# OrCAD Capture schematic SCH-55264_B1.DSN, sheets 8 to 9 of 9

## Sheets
8 07 LVDS_CONNECTORS: size C
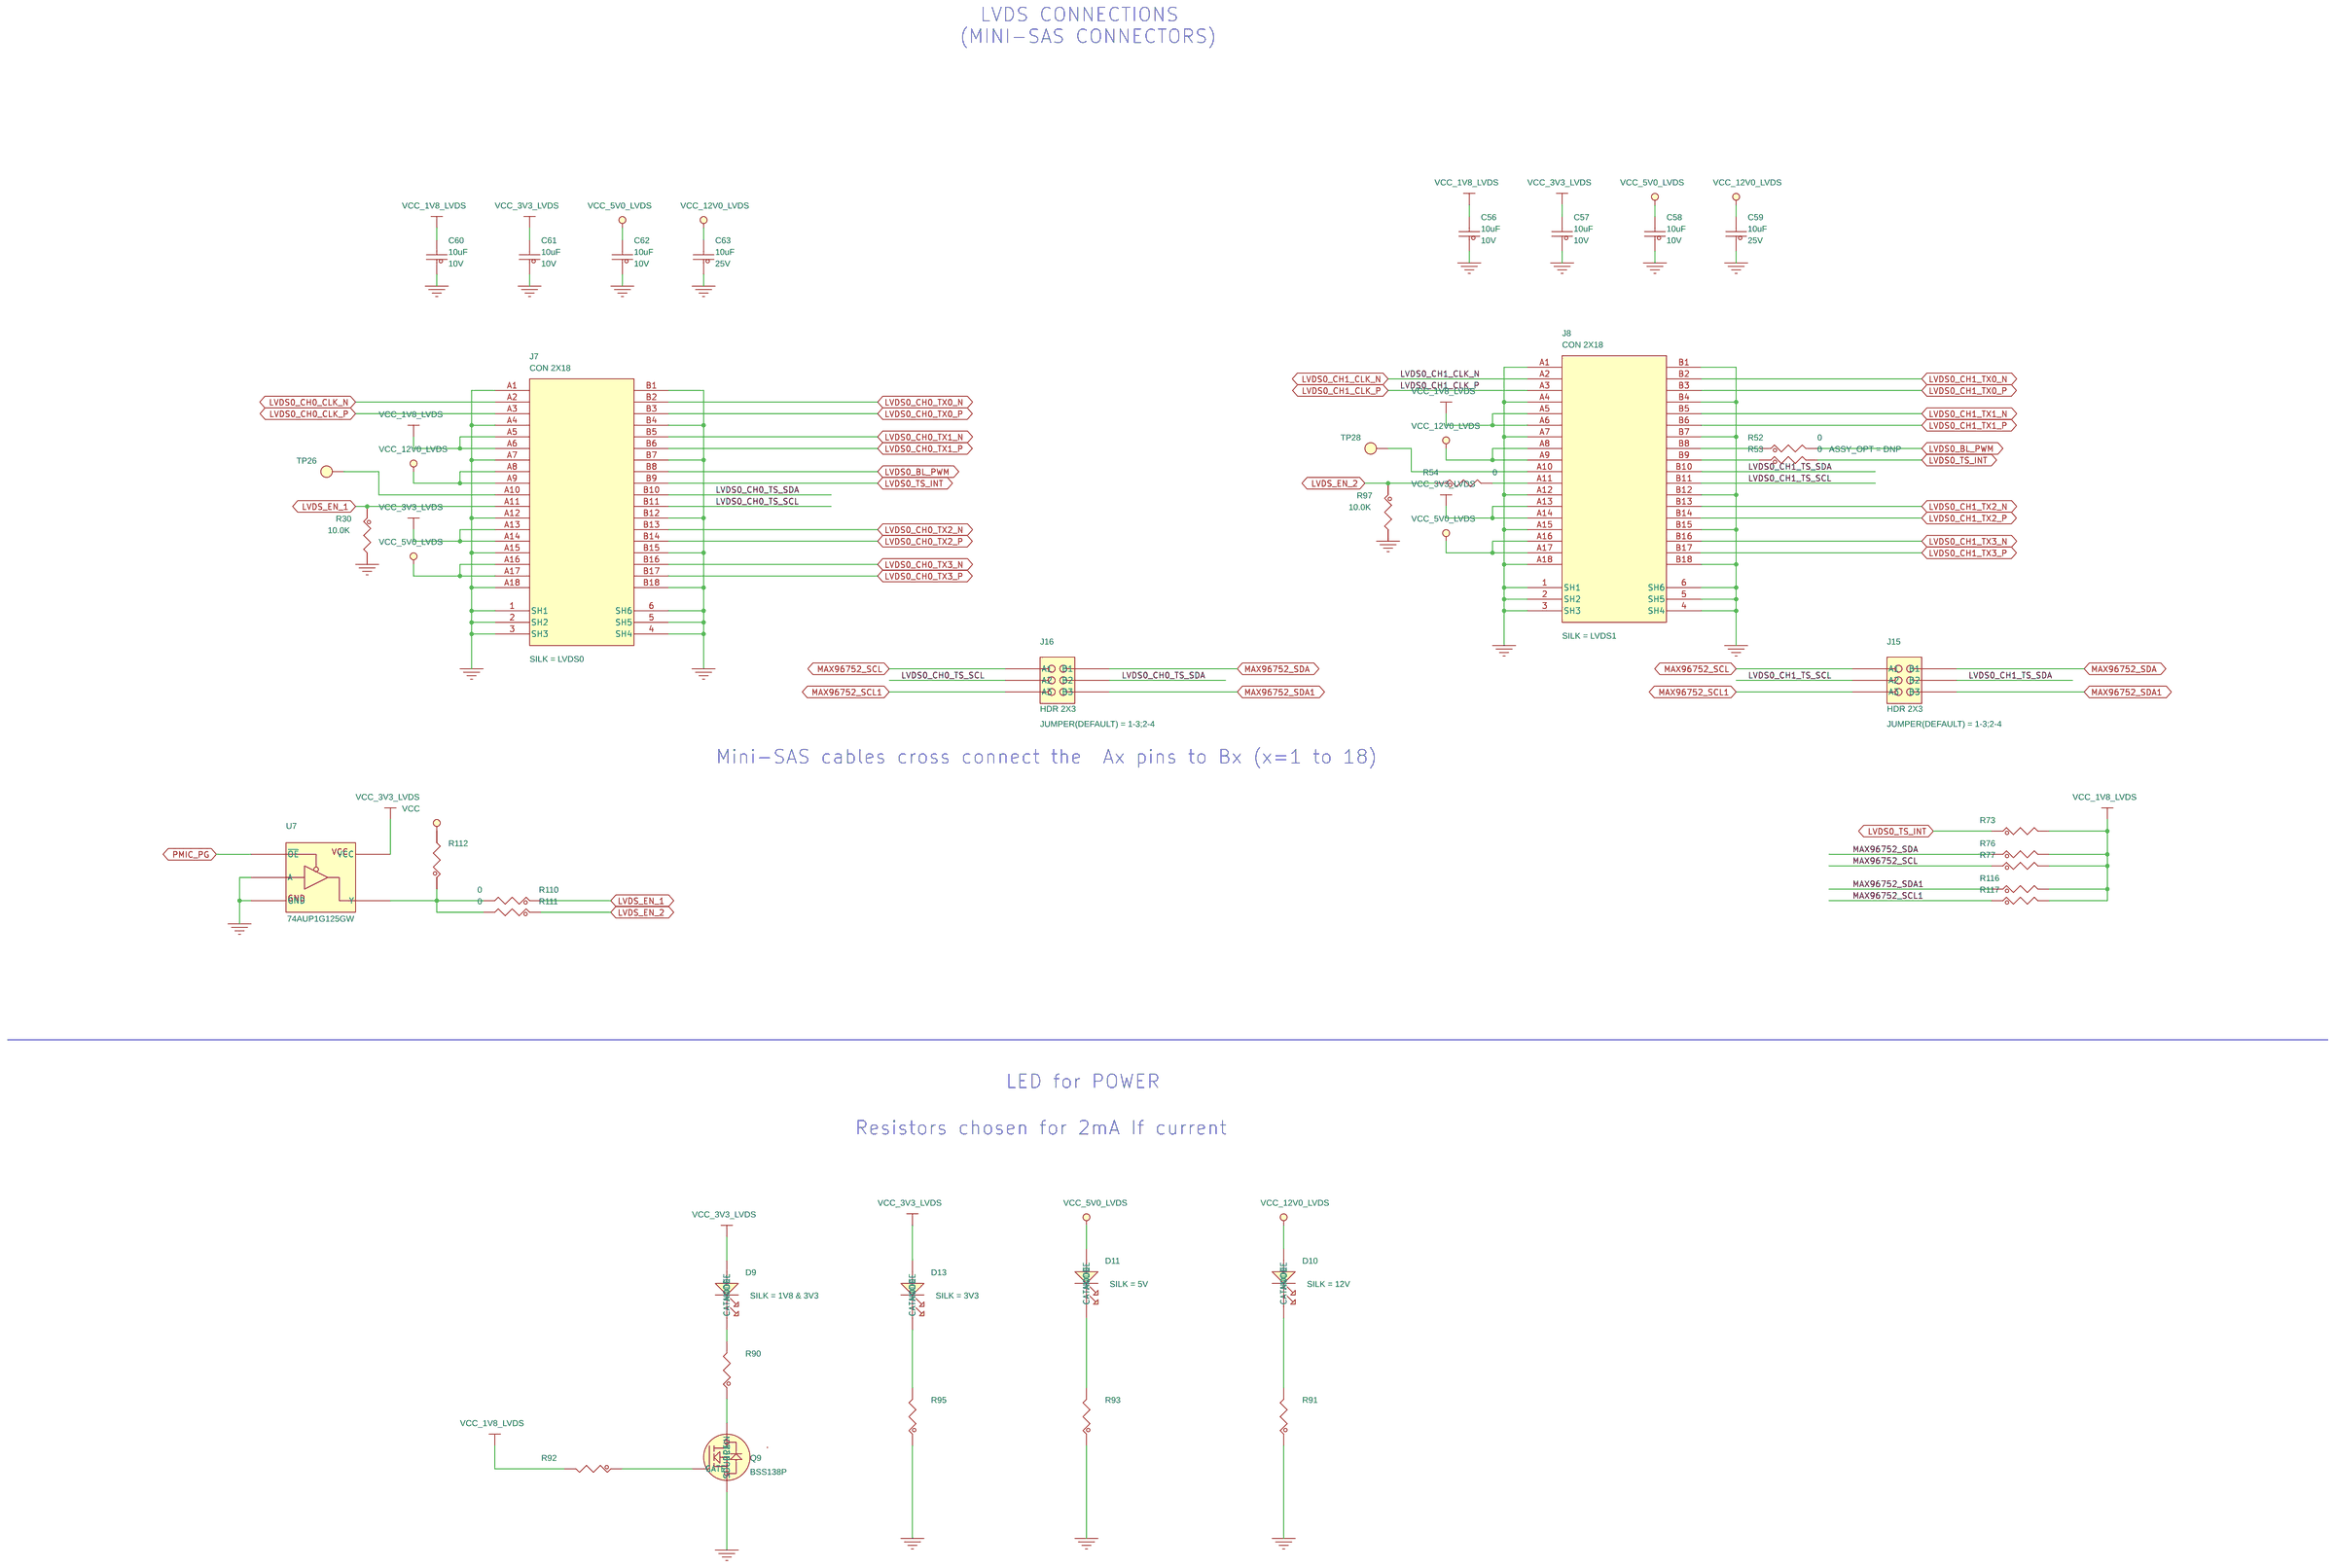
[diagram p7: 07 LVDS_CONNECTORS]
9 08 PMIC_LVDS_SUPPLIES: size C
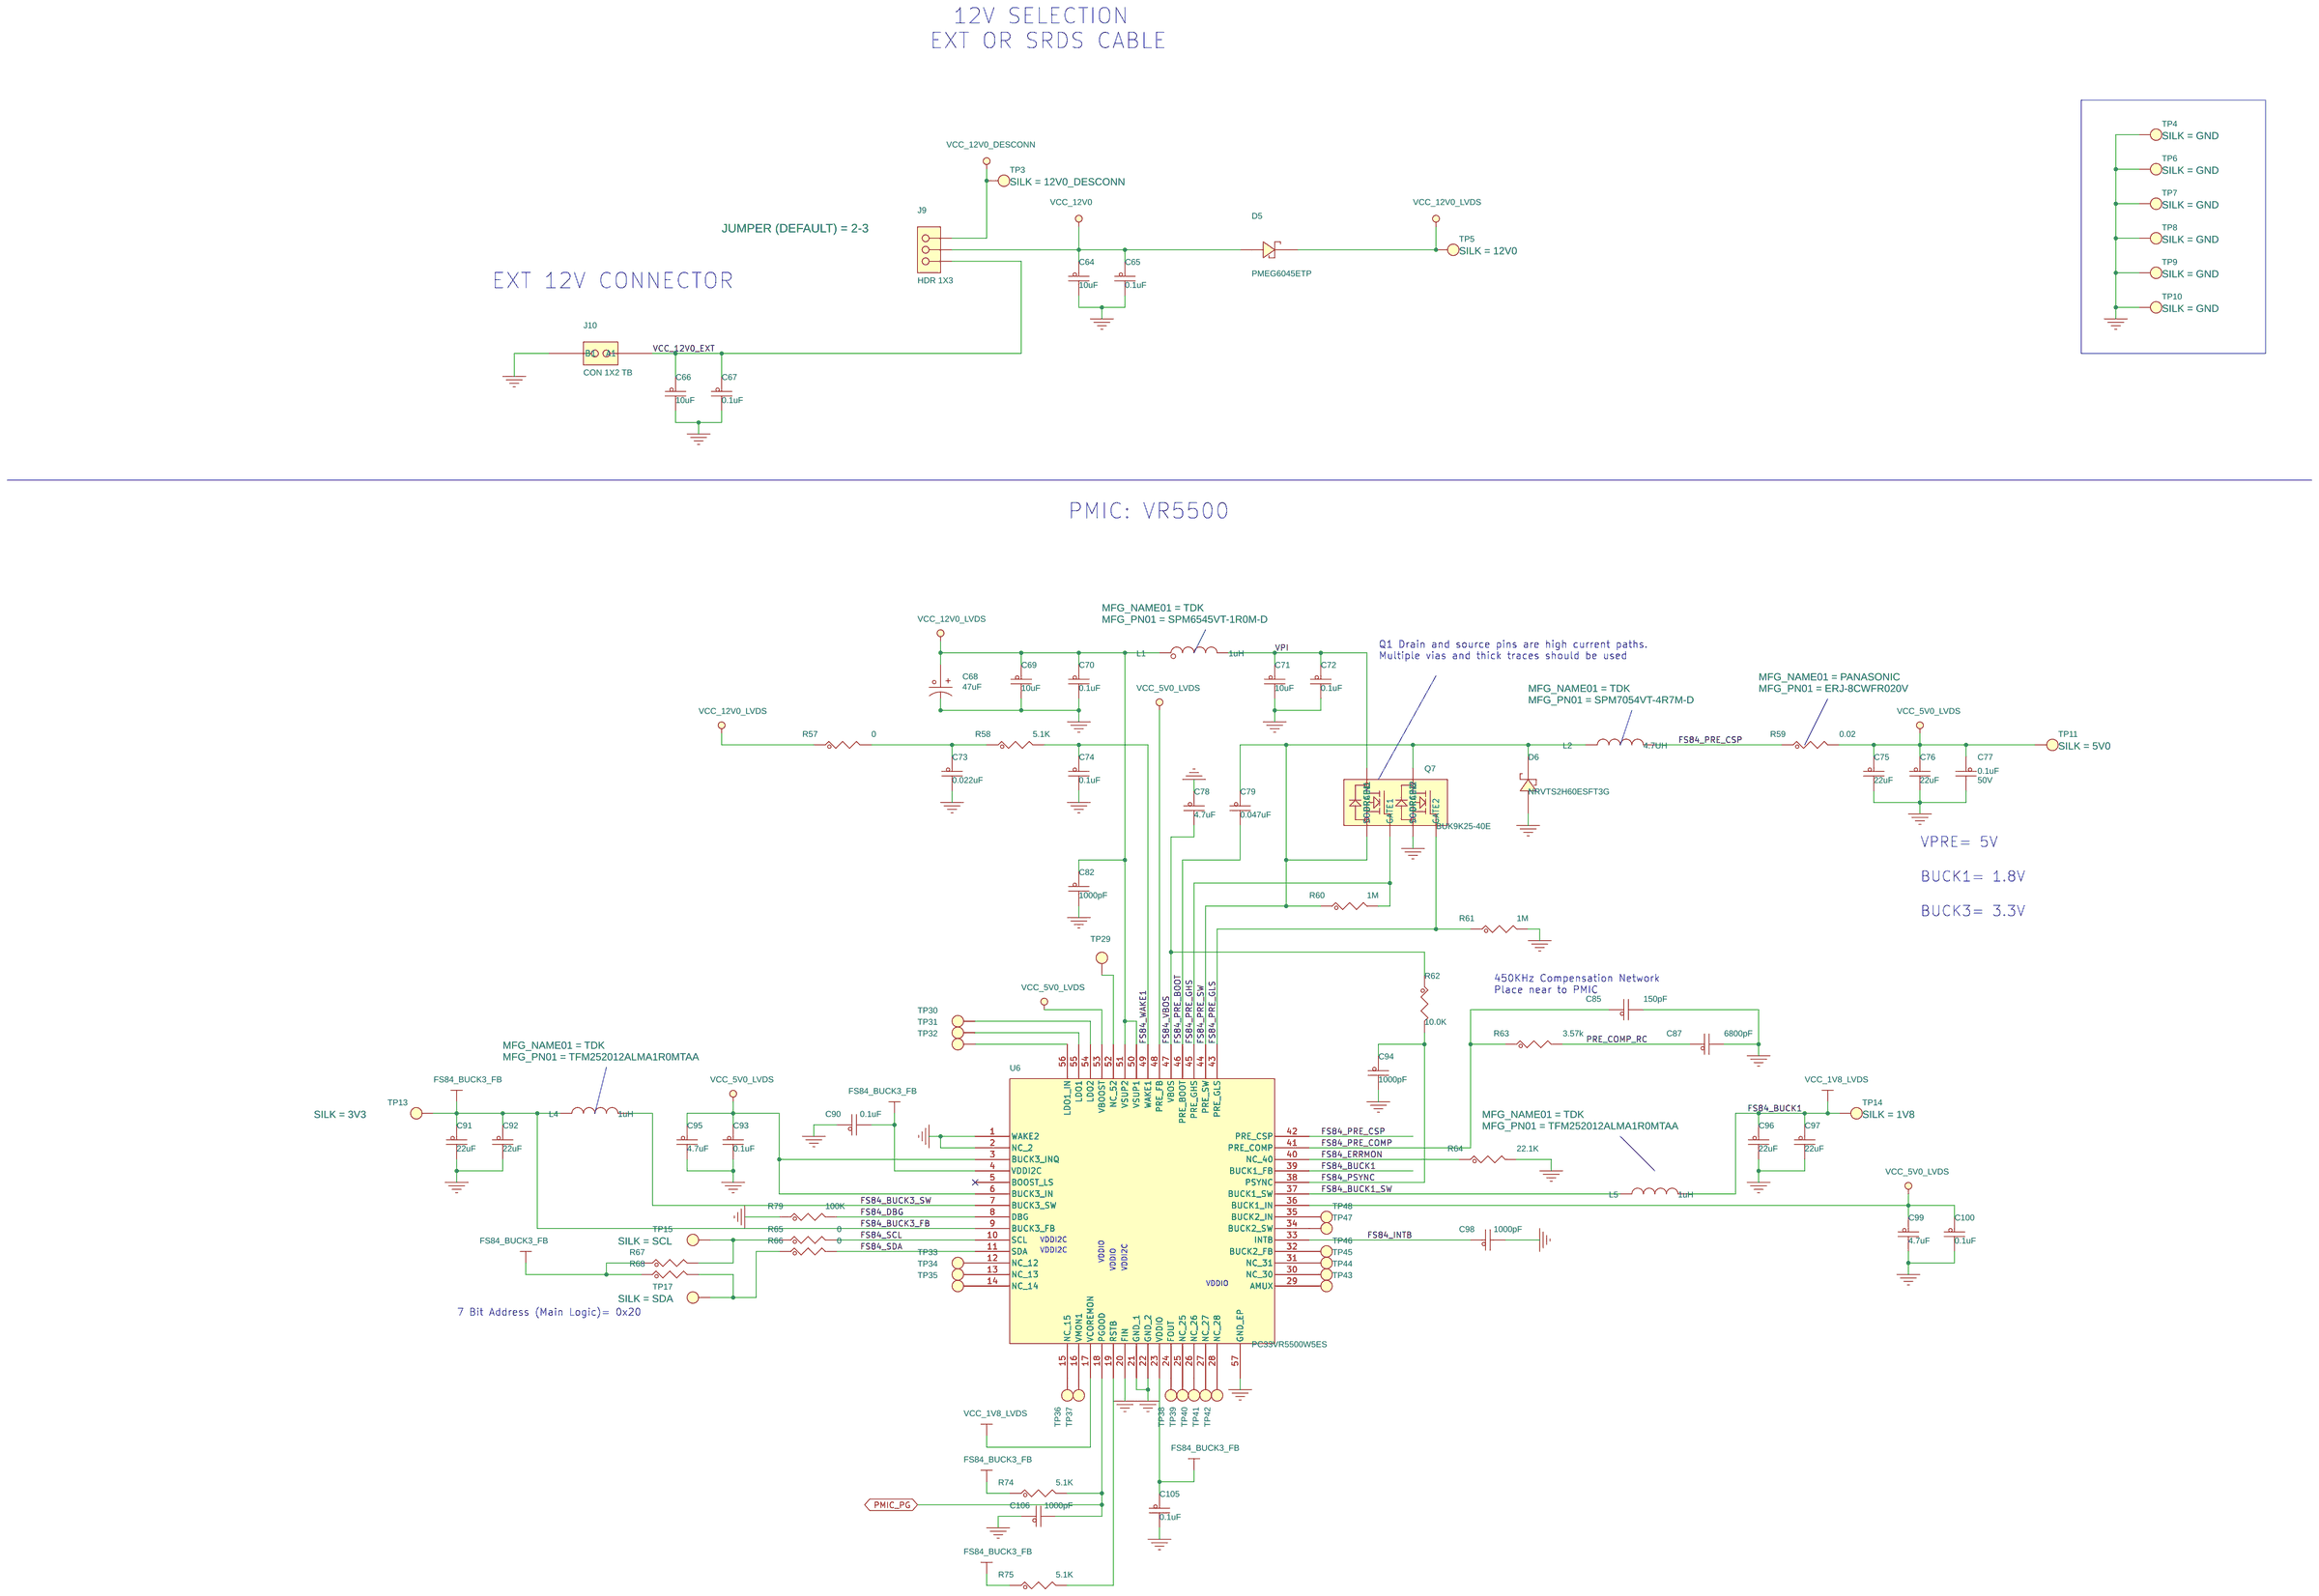
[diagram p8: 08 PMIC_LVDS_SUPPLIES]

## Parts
sheet 07 LVDS_CONNECTORS
C56  10uF  [CC0603_OV]
C57  10uF  [CC0603_OV]
C58  10uF  [CC0603_OV]
C59  10uF  [CC0603_OV]
C60  10uF  [CC0603_OV]
C61  10uF  [CC0603_OV]
C62  10uF  [CC0603_OV]
C63  10uF  [CC0603_OV]
D9  LED GREEN  [LED_0603]
D10  LED GREEN  [LED_0603]
D11  LED GREEN  [LED_0603]
D13  LED GREEN  [LED_0603]
J7  CON 2X18  [con2x18_recep_wshell_0p8_sm_ra]
J8  CON 2X18  [con2x18_recep_wshell_0p8_sm_ra]
J15  HDR 2X3  [HDR203]
J16  HDR 2X3  [HDR203]
Q9  BSS138P  [sot23_a]
R30  10.0K  [RC0402_25]
R52  0  [RC0402_25]
R53  0  [RC0402_25]
R54  0  [RC0402_25]
R73  4.7K  [RC0402_25]
R76  4.7K  [RC0402_25]
R77  4.7K  [RC0402_25]
R90  1.00k  [RC0402_25]
R91  5.23K  [RC0402_25]
R92  1.00k  [RC0402_25]
R93  1.5K  [RC0402_25]
R95  1.00k  [RC0402_25]
R97  10.0K  [RC0402_25]
R110  0  [RC0402_25]
R111  0  [RC0402_25]
R112  1.00k  [RC0402_25]
R116  4.7K  [RC0402_25]
R117  4.7K  [RC0402_25]
TP26  TP_35MIL  [testpoint_35mil]
TP28  TP_35MIL  [testpoint_35mil]
U7  74AUP1G125GW  [SC70-5]
sheet 08 PMIC_LVDS_SUPPLIES
C64  10uF  [CC1210]
C65  0.1uF  [CC0402_25]
C66  10uF  [CC1210]
C67  0.1uF  [CC0402_25]
C68  47uF  [case_d]
C69  10uF  [CC1210]
C70  0.1uF  [CC0402_25]
C71  10uF  [CC1210]
C72  0.1uF  [CC0402_25]
C73  0.022uF  [CC0402_25]
C74  0.1uF  [CC0402_25]
C75  22uF  [CC1210]
C76  22uF  [CC1210]
C77  0.1uF  [CC0402_25]
C78  4.7uF  [CC0805_OV]
C79  0.047uF  [CC0402_25]
C82  1000pF  [CC0402_25]
C85  150pF  [CC0402_25]
C87  6800pF  [CC0402_25]
C90  0.1uF  [CC0402_25]
C91  22uF  [CC1210]
C92  22uF  [CC1210]
C93  0.1uF  [CC0402_25]
C94  1000pF  [CC0402_25]
C95  4.7uF  [CC0805_OV]
C96  22uF  [CC1210]
C97  22uF  [CC1210]
C98  1000pF  [CC0402_25]
C99  4.7uF  [CC0805_OV]
C100  0.1uF  [CC0402_25]
C105  0.1uF  [CC0402_25]
C106  1000pF  [CC0402_25]
D5  PMEG6045ETP  [sod-128]
D6  NRVTS2H60ESFT3G  [sod-123]
J9  HDR 1X3  [hdr103_a_344h]
J10  CON 1X2 TB  [con_tb_1x2_5p08_ra_th]
L1  1uH  [ind2_7p4x6p9_sm]
L2  4.7UH  [ind2_7p5x7]
L4  1uH  [ind2520]
L5  1uH  [ind2520]
Q7  BUK9K25-40E  [LFPAK56_1P27_4P7X5P3]
R57  0  [RC0402_25]
R58  5.1K  [RC0402_25]
R59  0.02  [RC1206_OV]
R60  1M  [RC0402_25]
R61  1M  [RC0402_25]
R62  10.0K  [RC0402_25]
R63  3.57k  [RC0402_25]
R64  22.1K  [RC0402_25]
R65  0  [RC0402_25]
R66  0  [RC0402_25]
R67  4.7K  [RC0402_25]
R68  4.7K  [RC0402_25]
R74  5.1K  [RC0402_25]
R75  5.1K  [RC0402_25]
R79  100K  [RC0603_OV]
TP3  TP_35MIL  [testpoint_35mil]
TP4  TP_35MIL  [testpoint_35mil]
TP5  TP_35MIL  [testpoint_35mil]
TP6  TP_35MIL  [testpoint_35mil]
TP7  TP_35MIL  [testpoint_35mil]
TP8  TP_35MIL  [testpoint_35mil]
TP9  TP_35MIL  [testpoint_35mil]
TP10  TP_35MIL  [testpoint_35mil]
TP11  TP_35MIL  [testpoint_35mil]
TP13  TP_35MIL  [testpoint_35mil]
TP14  TP_35MIL  [testpoint_35mil]
TP15  TP_35MIL  [testpoint_35mil]
TP17  TP_35MIL  [testpoint_35mil]
TP29  TP_35MIL  [testpoint_35mil]
TP30  TP_35MIL  [testpoint_35mil]
TP31  TP_35MIL  [testpoint_35mil]
TP32  TP_35MIL  [testpoint_35mil]
TP33  TP_35MIL  [testpoint_35mil]
TP34  TP_35MIL  [testpoint_35mil]
TP35  TP_35MIL  [testpoint_35mil]
TP36  TP_35MIL  [testpoint_35mil]
TP37  TP_35MIL  [testpoint_35mil]
TP38  TP_35MIL  [testpoint_35mil]
TP39  TP_35MIL  [testpoint_35mil]
TP40  TP_35MIL  [testpoint_35mil]
TP41  TP_35MIL  [testpoint_35mil]
TP42  TP_35MIL  [testpoint_35mil]
TP43  TP_35MIL  [testpoint_35mil]
TP44  TP_35MIL  [testpoint_35mil]
TP45  TP_35MIL  [testpoint_35mil]
TP46  TP_35MIL  [testpoint_35mil]
TP47  TP_35MIL  [testpoint_35mil]
TP48  TP_35MIL  [testpoint_35mil]
U6  PC33VR5500W5ES  [qfn56_0p5_8x8_ep4p39]

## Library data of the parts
C56-C58 C60-C62 = CAP_NP: CAP CER 10uF 25V 20% X5R 0603; AGILE_PN: 150-79272; CAD_APPROVED: Yes; EN: 102-1-01640; FPLIST: CC0603_OV,CC0603,0603_CC; HEIGHT: 1; MFG_NAME01: MURATA; MFG_PN01: GRM188R61E106MA73D; Package Size: 0603; ROHS: Yes; Rated Voltage: 25V; Temp Range: -55C to +85C; Tolerance: 20%; VOLTAGE: 10V
C59 C63 = CAP_NP: CAP CER 10uF 25V 20% X5R 0603; AGILE_PN: 150-79272; CAD_APPROVED: Yes; EN: 102-1-01982; FPLIST: CC0603_OV,CC0603,0603_CC; HEIGHT: 1; MFG_NAME01: MURATA; MFG_PN01: GRM188R61E106MA73D; Package Size: 0603; ROHS: Yes; Rated Voltage: 25V; TOL: 20%; Temp Range: -55C to +85C; Tolerance: 20%; VOLTAGE: 25V
D9 = LED: LED GRN SGL 20MA SMT; AGILE_PN: 370-75722; CAD_APPROVED: Yes; HEIGHT: 0.8; MFG_NAME01: AVAGO TECHNOLOGIES; MFG_PN01: HSMG-C190; ROHS: Yes; Rated Voltage: 2.6V; SILK: 1V8 & 3V3; Temp Range: -30°C to +85°C; VOLTAGE: 2.6V
D10 = LED: LED GRN SGL 20MA SMT; AGILE_PN: 370-75722; CAD_APPROVED: Yes; HEIGHT: 0.8; MFG_NAME01: AVAGO TECHNOLOGIES; MFG_PN01: HSMG-C190; ROHS: Yes; Rated Voltage: 2.6V; SILK: 12V; Temp Range: -30°C to +85°C; VOLTAGE: 2.6V
D11 = LED: LED GRN SGL 20MA SMT; AGILE_PN: 370-75722; CAD_APPROVED: Yes; HEIGHT: 0.8; MFG_NAME01: AVAGO TECHNOLOGIES; MFG_PN01: HSMG-C190; ROHS: Yes; Rated Voltage: 2.6V; SILK: 5V; Temp Range: -30°C to +85°C; VOLTAGE: 2.6V
D13 = LED: LED GRN SGL 20MA SMT; AGILE_PN: 370-75722; CAD_APPROVED: Yes; HEIGHT: 0.8; MFG_NAME01: AVAGO TECHNOLOGIES; MFG_PN01: HSMG-C190; ROHS: Yes; Rated Voltage: 2.6V; SILK: 3V3; Temp Range: -30°C to +85°C; VOLTAGE: 2.6V
J7 = CON_2X18_SH6: CON 2X18 RA SKT W/SHELL SMT 0.8MM SP 339H AU; 3D_Mechanical_Footprint_File: http://fcl.am.freescale.net/ALLEGRO/step/con2x18_recep_wshell_0p8_sm_ra.STEP; AGILE_PN: 211-80139; CAD_APPROVED: Yes; EN: 201-1-00825; HEIGHT: 8.6; MFG_NAME01: MOLEX; MFG_PN01: 075783-0132; ROHS: NULL; SILK: LVDS0; Temp Range: -40 °C to +80 °C
J8 = CON_2X18_SH6: CON 2X18 RA SKT W/SHELL SMT 0.8MM SP 339H AU; 3D_Mechanical_Footprint_File: http://fcl.am.freescale.net/ALLEGRO/step/con2x18_recep_wshell_0p8_sm_ra.STEP; AGILE_PN: 211-80139; CAD_APPROVED: Yes; EN: 201-1-00825; HEIGHT: 8.6; MFG_NAME01: MOLEX; MFG_PN01: 075783-0132; ROHS: NULL; SILK: LVDS1; Temp Range: -40 °C to +80 °C
J15 J16 = CONN_HDR_3X2: HDR 2X3 TH 100MIL CTR 338H AU 100L; 3D_Mechanical_Footprint_File: http://fcl.am.freescale.net/ALLEGRO/step/hdr203.STEP; AGILE_PN: 210-81396; CAD_APPROVED: Yes; HEIGHT: 8.59; JUMPER(DEFAULT): 1-3;2-4; MFG_NAME01: SAMTEC; MFG_PN01: TSW-103-07-G-D; Package Size: 7.62x5.08m; ROHS: Yes; Temp Range: -55C to +125C
Q9 = MOSFET_N: TRAN NMOS 60V 360MA AEC-Q101 TO-236AB; AGILE_PN: 480-79842; CAD_APPROVED: Yes; HEIGHT: 1.1; MFG_NAME01: NEXPERIA; MFG_PN01: BSS138P,215; ROHS: Yes; Temp Range: -65°C ~ 150°C
R30 R97 = RES: RES MF 10.0K 1/16W 1% AEC-Q200 0402; AGILE_PN: 470-75416; CAD_APPROVED: Yes; HEIGHT: 0.4; MFG_NAME01: KOA SPEER; MFG_PN01: RK73H1ETTP1002F; ROHS: Yes; Temp Range: –55 °C to +155 °C; Tolerance: 1%
R52 R54 R110 R111 = RES: RES MF ZERO OHM 1/16W -- AEC-Q200 0402; AGILE_PN: 470-80742; CAD_APPROVED: Yes; HEIGHT: 0.45; MFG_NAME01: VISHAY INTERTECHNOLOGY; MFG_PN01: CRCW04020000Z0ED; ROHS: NULL; Temp Range: -55° C to +155° C
R53 = RES: RES MF ZERO OHM 1/16W -- AEC-Q200 0402; AGILE_PN: 470-80742; ASSY_OPT: DNP; CAD_APPROVED: Yes; HEIGHT: 0.45; MFG_NAME01: VISHAY INTERTECHNOLOGY; MFG_PN01: CRCW04020000Z0ED; ROHS: NULL; Temp Range: -55° C to +155° C
R67 R68 R73 R76 R77 R116 R117 = RES: RES MF 4.7K 1/10W 1% AEC-Q200 0402; AGILE_PN: 470-81976; CAD_APPROVED: Yes; FPLIST: RC0402_25,RC0402_HD,0402_CC; HEIGHT: 0.4; MFG_NAME01: KOA SPEER; MFG_PN01: RK73H1ETTP4701F; ROHS: Yes; SIGNAL_MODEL: DEFAULT_RESISTOR_4700OHM_2_1; Temp Range: -55C to +155C; Tolerance: 1%; VOLTAGE: 50V
R90 R92 R95 R112 = RES: RES MF 1.00k Ohm 1/16W 1% AEC-Q200 0402; 3D_Mechanical_Footprint_File: http://fcl.am.freescale.net/ALLEGRO/step/rc0402_25.STEP; AGILE_PN: 470-80511; CAD_APPROVED: Yes; FPLIST: RC0402_25,RC0402_HD,0402_CC; HEIGHT: 0.4; MFG_NAME01: KOA SPEER; MFG_PN01: RK73H1ETTP1001F; ROHS: Yes; Tolerance: 1%; VOLTAGE: 50V
R91 = RES: RES MF 5.23K  1/10W 1% AEC-Q200 0402; AGILE_PN: 470-81644; CAD_APPROVED: Yes; FPLIST: RC0402_25,RC0402_HD,0402_CC; HEIGHT: 0.40; MFG_NAME01: KOA SPEER; MFG_PN01: RK73H1ETTP5231F; ROHS: Yes; Temp Range: -55C to +155C; Tolerance: 1%; VOLTAGE: 50V
R93 = RES: RES MF 1.50K 1/16W 1% AEC-Q200 0402; AGILE_PN: 470-81991; CAD_APPROVED: Yes; FPLIST: RC0402_25,RC0402_HD,0402_CC; HEIGHT: 0.4; MFG_NAME01: VISHAY INTERTECHNOLOGY; MFG_PN01: CRCW04021K50FKED; ROHS: Yes; Temp Range: -55C to +155C; Tolerance: 1%; VOLTAGE: 50V
TP26 TP28-TP48 = T_POINT_R: TEST POINT PAD .035 SMT, no part to order; AGILE_PN: 510-75618; CAD_APPROVED: Yes; HEIGHT: 0.1; ROHS: Yes
U7 = 1G125: IC BUFFER/LINE DRIVER 3STATE 0.8-3.6V SC70-5; 3D_Mechanical_Footprint_File: http://fcl.am.freescale.net/ALLEGRO/step/sc70-5.STEP; AGILE_PN: 315-80956; CAD_APPROVED: Yes; HEIGHT: 1.1; MFG_NAME01: NEXPERIA; MFG_PN01: 74AUP1G125GW,125; ROHS: NULL; Temp Range: -40° C to +125° C; VOLTAGE: 0.8-3.6V
C64 C66 C69 = CAP_NP: CAP CER 10uF 50V 10% X7S AEC-Q200 1210; AGILE_PN: 150-79213; CAD_APPROVED: Yes; FPLIST: CC1210,1210_CC; HEIGHT: 2.8; MFG_NAME01: MURATA; MFG_PN01: GCM32EC71H106KA03; Package Size: 1210; ROHS: Yes; Rated Voltage: 50V; Temp Range: -55C to +125C; Tolerance: 10%; VOLTAGE: 50V
C65 C67 C70 C74 C90 C93 C100 C105 = CAP_NP: CAP CER 0.1uF 50V 10% X7R AEC-Q200 0402; AGILE_PN: 150-79461; CAD_APPROVED: Yes; FPLIST: CC0402_25,CC0402_HD,0402_CC; HEIGHT: 0.55; MFG_NAME01: MURATA; MFG_PN01: GCM155R71H104KE02D; Package Size: 0402; ROHS: NULL; Rated Voltage: 50V; Temp Range: -55C to +125C; Tolerance: 10%; VOLTAGE: 50V
C68 = CAP_POL: CAP TANT 47UF 25V 10% SIZE D; 3D_Mechanical_Footprint_File: http://fcl.am.freescale.net/ALLEGRO/step/CASE_D.step; AGILE_PN: 150-75813; CAD_APPROVED: Yes; HEIGHT: 3.2; MFG_NAME01: AVX; MFG_PN01: TPSD476K025R0125; Package Size: 7343; Package Type: 7" T/R; ROHS: Yes; Rated Voltage: 25V; Tolerance: 10%; VOLTAGE: 25V
C71 = CAP_NP: CAP CER 10uF 50V 10% X7S AEC-Q200 1210; AGILE_PN: 150-79213; CAD_APPROVED: Yes; FPLIST: CC1210,1210_CC; HARD_LOCATION: YES; HEIGHT: 2.8; MFG_NAME01: MURATA; MFG_PN01: GCM32EC71H106KA03; Package Size: 1210; ROHS: Yes; Rated Voltage: 50V; Temp Range: -55C to +125C; Tolerance: 10%; VOLTAGE: 50V
C72 = CAP_NP: CAP CER 0.1uF 50V 10% X7R AEC-Q200 0402; AGILE_PN: 150-79461; CAD_APPROVED: Yes; FPLIST: CC1210,1210_CC; HARD_LOCATION: YES; HEIGHT: 0.55; MFG_NAME01: MURATA; MFG_PN01: GCM155R71H104KE02D; Package Size: 0402; ROHS: NULL; Rated Voltage: 50V; Temp Range: -55C to +125C; Tolerance: 10%; VOLTAGE: 50V
C73 = CAP_NP: CAP CER 0.022uF 50V 10% X7R AEC-Q200 0402; AGILE_PN: 150-79037; CAD_APPROVED: Yes; FPLIST: CC0402_25,CC0402_HD,0402_CC; HEIGHT: 0.55; MFG_NAME01: MURATA; MFG_PN01: GCM155R71H223KA55D; Package Size: 0402; Package Type: Paper tape; ROHS: Yes; Rated Voltage: 50V; Temp Range: -55C to +125C; Tolerance: 10%; VOLTAGE: 50V
C75 C76 = CAP_NP: CAP CER 22uF 25V 10% X7S AEC-Q200 1210; 3D_Mechanical_Footprint_File: http://fcl.am.freescale.net/ALLEGRO/step/cc1210.STEP; AGILE_PN: 150-79912; CAD_APPROVED: Yes; HARD_LOCATION: YES; HEIGHT: 2.85; MFG_NAME01: MURATA; MFG_PN01: GCM32EC71E226KE36#; Package Size: 1210; ROHS: Yes; Rated Voltage: 25V; Temp Range: -55C to +125C; Tolerance: 10%; VOLTAGE: 25V
C77 = CAP_NP: CAP CER 0.1uF 50V 10% X7R AEC-Q200 0402; AGILE_PN: 150-79461; CAD_APPROVED: Yes; HEIGHT: 0.55; MFG_NAME01: MURATA; MFG_PN01: GCM155R71H104KE02D; Package Size: 0402; ROHS: NULL; Rated Voltage: 50V; Temp Range: -55C to +125C; Tolerance: 10%; VOLTAGE: 50V
C78 C95 C99 = CAP_NP: CAP CER 4.7uF 35V 10% X7S AEC-Q200 0805; AGILE_PN: 150-79910; CAD_APPROVED: Yes; FPLIST: CC0805_OV,CC0805,0805_CC; HEIGHT: 1.45; MFG_NAME01: MURATA; MFG_PN01: GCM21BC7YA475KE36; Package Size: 0805; ROHS: Yes; Rated Voltage: 35V; Temp Range: -55C to +125C; Tolerance: 10%; VOLTAGE: 35V
C79 = CAP_NP: CAP CER 0.047uF 50V 10% X7R AEC-Q200 0402; AGILE_PN: 150-79340; CAD_APPROVED: Yes; FPLIST: CC0402_25,CC0402_HD,0402_CC; HARD_LOCATION: YES; HEIGHT: 0.55; MFG_NAME01: TDK; MFG_PN01: CGA2B3X7R1H473K050BB; ROHS: Yes; Rated Voltage: 50V; Temp Range: -55C to +125C; Tolerance: 10%; VOLTAGE: 50V
C82 = CAP_NP: CAP CER 1000pF 50V 10% X7R AEC-Q200 0402; AGILE_PN: 150-79040; CAD_APPROVED: Yes; FPLIST: CC0402_25,CC0402_HD,0402_CC,capc0402_l; HEIGHT: 0.55; MFG_NAME01: MURATA; MFG_PN01: GCM155R71H102KA37D; Package Size: 0402; Package Type: Paper Tape; ROHS: Yes; Rated Voltage: 50V; Temp Range: -55C to +125C; Tolerance: 10%; VOLTAGE: 50V
C85 = CAP_NP: CAP CER 150pF 50V 5% C0G AEC-Q200 0402; AGILE_PN: 150-79027; CAD_APPROVED: Yes; HEIGHT: 0.55; MFG_NAME01: MURATA; MFG_PN01: GCM1555C1H151JA16D; Package Size: 0402; Package Type: Paper Tape; ROHS: Yes; Rated Voltage: 50V; Temp Range: -55C to +125C; Tolerance: 5%; VOLTAGE: 50V
C87 = CAP_NP: CAP CER 6800pF 50V 10% X7R AEC-Q200 0402; AGILE_PN: 150-80718; CAD_APPROVED: Yes; HEIGHT: 0.5; MFG_NAME01: TDK; MFG_PN01: CGA2B2X7R1H682K050BA; Package Size: 0402 (1005 metric); Package Type: SMD/SMT; ROHS: Yes; Rated Voltage: 50V; Temp Range: -55C to +125C; Tolerance: 10%; VOLTAGE: 50V
C91 C92 C96 C97 = CAP_NP: CAP CER 22uF 25V 10% X7S AEC-Q200 1210; 3D_Mechanical_Footprint_File: http://fcl.am.freescale.net/ALLEGRO/step/cc1210.STEP; AGILE_PN: 150-79912; CAD_APPROVED: Yes; HEIGHT: 2.85; MFG_NAME01: MURATA; MFG_PN01: GCM32EC71E226KE36#; Package Size: 1210; ROHS: Yes; Rated Voltage: 25V; Temp Range: -55C to +125C; Tolerance: 10%; VOLTAGE: 25V
C94 = CAP_NP: CAP CER 1000pF 50V 10% X7R AEC-Q200 0402; AGILE_PN: 150-79040; CAD_APPROVED: Yes; FPLIST: CC0402_25,CC0402_HD,0402_CC; HEIGHT: 0.55; MFG_NAME01: MURATA; MFG_PN01: GCM155R71H102KA37D; Package Size: 0402; Package Type: Paper Tape; ROHS: Yes; Rated Voltage: 50V; Temp Range: -55C to +125C; Tolerance: 10%; VOLTAGE: 50V
C98 C106 = CAP_NP: CAP CER 1000pF 50V 10% X7R AEC-Q200 0402; AGILE_PN: 150-79040; CAD_APPROVED: Yes; FPLIST: CC0603_OV,CC0603,0603_CC; HEIGHT: 0.55; MFG_NAME01: MURATA; MFG_PN01: GCM155R71H102KA37D; Package Size: 0402; Package Type: Paper Tape; ROHS: Yes; Rated Voltage: 50V; Temp Range: -55C to +125C; Tolerance: 10%; VOLTAGE: 50V
D5 = DIODE_SCHTKY: DIODE SCHOTTKY 60V 4.5A AEC-Q101 SOD128; AGILE_PN: 480-79703; CAD_APPROVED: Yes; HEIGHT: 1.1; MFG_NAME01: NEXPERIA; MFG_PN01: PMEG6045ETPX
D6 = DIODE_SCHTKY: DIODE SCH PWR RECT 2A 60V AEC-Q101 SOD-123; 3D_Mechanical_Footprint_File: http://fcl.am.freescale.net/ALLEGRO/step/sod-123.STEP; AGILE_PN: 480-80485; CAD_APPROVED: YES; HEIGHT: 0.98; MFG_NAME01: ON Semiconductor; Package Size: SOD-123F; ROHS: Yes; Rated Voltage: 60V; Temp Range: -65 C TO -175 C; Temp_Range: -65C to +175C; VOLTAGE: 60V
J9 = CONN_HDR_3X1: HDR 1X3 TH 2.54MM SP 344H AU 118L; 3D_Mechanical_Footprint_File: http://fcl.am.freescale.net/ALLEGRO/step/hdr103_a_344h.STEP; AGILE_PN: 210-80732; CAD_APPROVED: Yes; HEIGHT: 8.74; JUMPER (DEFAULT): 2-3; MFG_NAME01: WURTH ELEKTRONIK EISOS GMBH & CO. KG (ELECTRONIC & ELECTROMEHANICAL COMP); MFG_PN01: 61300311121; ROHS: Yes; Temp Range: -40°C to +105°C
J10 = CONN_HDR_1X2: CON 1X2 TB TH 5.08MM 346H SN 138L; 3D_Mechanical_Footprint_File: http://fcl.am.freescale.net/ALLEGRO/step/con_tb_1x2_5p08_ra_th.STEP; AGILE_PN: 210-82654; CAD_APPROVED: Yes; Contact Voltage: 300 V(AC); HEIGHT: 8.8; MFG_NAME01: WURTH ELEKTRONIK EISOS GMBH & CO. KG (ELECTRONIC & ELECTROMEHANICAL COMP); MFG_PN01: 691313510002; Package Type: Through Hole; ROHS: Yes; Temp Range: -40C to +105C
L1 = INDP: IND PWR 1.0uH@100KHz 17.9A 20% AEC-Q200 SMD; 3D_Mechanical_Footprint_File: http://fcl.am.freescale.net/ALLEGRO/step/ind2_7p4x6p9_sm.STEP; AGILE_PN: 180-78579; CAD_APPROVED: Yes; HEIGHT: 4.5; MFG_NAME01: TDK; MFG_PN01: SPM6545VT-1R0M-D; PART_TYPE: INDUCTOR\POWER; ROHS: Yes; TOL: 20%; Temp Range: -55ºC ~ +150ºC; Temp_Range: -55ºC ~ +150ºC; Tolerance: 20%
L2 = INDUCTOR: IND PWR 4.7uH 11.2A 20% AEC-Q200 SMD; 3D_Mechanical_Footprint_File: http://fcl.am.freescale.net/ALLEGRO/step/ind2_7p5x7.STEP; AGILE_PN: 180-78642; CAD_APPROVED: Yes; HEIGHT: 5.4; MFG_NAME01: TDK; MFG_PN01: SPM7054VT-4R7M-D; PART_TYPE: INDUCTOR\POWER; Package Size: 7.5x7x5.4 mm; ROHS: Yes; Temp Range: -55C to +150C; Temp_Range: -55 to 155 C; Tolerance: 10%
L4 L5 = INDUCTOR: IND PWR 1.0uH@1MHZ 4.7A 20% AEC-Q200 SMD; 3D_Mechanical_Footprint_File: http://fcl.am.freescale.net/ALLEGRO/step/ind2520.STEP; AGILE_PN: 180-78525; CAD_APPROVED: Yes; HARD_LOCATION: YES; HEIGHT: 1.2; MFG_NAME01: TDK; MFG_PN01: TFM252012ALMA1R0MTAA; PART_TYPE: INDUCTOR\POWER; ROHS: Yes; TOL: 20%; Tolerance: 20%
Q7 = NMOS_DUAL_8P: TRAN NMOS PWR SW DUAL 29mOHM 18.2A 40V AEC-Q101 LFPAK56D; 3D_Mechanical_Footprint_File: http://fcl.am.freescale.net/ALLEGRO/step/lfpak56_1p27_4p7x5p3.STEP; AGILE_PN: 480-79195; CAD_APPROVED: Yes; HEIGHT: 1.15; MFG_NAME01: NEXPERIA; MFG_PN01: BUK9K25-40EX; ROHS: Yes
R57 = RES: RES MF ZERO OHM 1/16W -- AEC-Q200 0402; AGILE_PN: 470-80742; CAD_APPROVED: Yes; FPLIST: RC0402_25,RC0402_HD,0402_CC; HEIGHT: 0.45; MFG_NAME01: VISHAY INTERTECHNOLOGY; MFG_PN01: CRCW04020000Z0ED; ROHS: NULL; Temp Range: -55° C to +155° C
R58 R74 = RES: RES MF 5.1K 1/10W 1% AEC-Q200 0402; AGILE_PN: 470-81628; CAD_APPROVED: Yes; FPLIST: RC0402_25,RC0402_HD,0402_CC; HEIGHT: 0.40; MFG_NAME01: KOA SPEER; MFG_PN01: RK73H1ETTP5101F; ROHS: Yes; TOL: 5%; Temp Coefficient - ppm/K: ± 200 ppm/K; Temp Range: -55°C to +155°C; Tolerance: 1%
R59 = RES: RES TF 0.02 OHM 1W 1% AEC-Q200 1206; AGILE_PN: 470-82185; CAD_APPROVED: Yes; FPLIST: RC1206_OV,RC1206,1206_CC; HEIGHT: 10.75; MFG_NAME01: PANASONIC; MFG_PN01: ERJ-8CWFR020V; ROHS: Yes; Temp Range: -55C to +125C; Temp_Range: -55C to +125C; Tolerance: 1%
R60 R61 = RES: RES MF 1.0M 1/16W 1% AEC-Q200 0402; 3D_Mechanical_Footprint_File: http://fcl.am.freescale.net/ALLEGRO/step/rc0402_25.STEP; AGILE_PN: 470-30000; CAD_APPROVED: Yes; FPLIST: RC0402_25,RC0402_HD,0402_CC; HEIGHT: 0.4; MFG_NAME01: VISHAY INTERTECHNOLOGY; MFG_PN01: CRCW04021M00FKED; ROHS: Yes; Temp Range: -55°C ~ 155°C; Temp_Range: -55°C ~ 155°C; Tolerance: 1%; VOLTAGE: 50V
R62 = RES: RES MF 10.0K 1/16W 1% AEC-Q200 0402; AGILE_PN: 470-75416; CAD_APPROVED: Yes; FPLIST: RC0402_25,RC0402_HD,0402_CC; HEIGHT: 0.4; MFG_NAME01: KOA SPEER; MFG_PN01: RK73H1ETTP1002F; ROHS: Yes; Temp Range: –55 °C to +155 °C; Tolerance: 1%
R63 = RES: RES MF 3.57K OHM 1/16W 0.1% AEC-Q200 0402; AGILE_PN: 470-82466; CAD_APPROVED: Yes; HEIGHT: 0.40; MFG_NAME01: PANASONIC; MFG_PN01: ERA2AEB3571X; ROHS: Yes; Temp Range: -55°Cto +155°C; Tolerance: 0.1%; VOLTAGE: 1/16W
R64 = RES: RES MF 22.1K 1/10W 1% AEC-Q200 0402; AGILE_PN: 470-30984; CAD_APPROVED: Yes; FPLIST: RC0402_25,RC0402_HD,0402_CC; HEIGHT: 0.40; MFG_NAME01: KOA SPEER; MFG_PN01: RK73H1ETTP2212F; ROHS: Yes; Temp Range: -55C to +155C; Temp_Range: -55C to +155C; Tolerance: 1%; VOLTAGE: 50V
R65 R66 = RES: RES MF ZERO OHM 1/16W -- AEC-Q200 0402; AGILE_PN: 470-80742; CAD_APPROVED: Yes; FPLIST: RC0402_25,RC0402_HD,RC0402_X2,0402_CC,CAPC0402_L; HEIGHT: 0.45; MFG_NAME01: VISHAY INTERTECHNOLOGY; MFG_PN01: CRCW04020000Z0ED; ROHS: NULL; Temp Range: -55° C to +155° C
R75 = RES: RES MF 5.1K 1/10W 1% AEC-Q200 0402; AGILE_PN: 470-81628; CAD_APPROVED: Yes; FPLIST: RC0402_25,RC0402_HD,0402_CC; HEIGHT: 0.40; MFG_NAME01: KOA SPEER; MFG_PN01: RK73H1ETTP5101F; ROHS: Yes; Temp Range: -55°C to +155°C; Tolerance: 1%
R79 = RES: RES MF 100K 1/4W 1% AEC-Q200 0603; AGILE_PN: 470-81181; CAD_APPROVED: Yes; FPLIST: RC0603_OV,RC0603,0603_CC; HEIGHT: 0.55; MFG_NAME01: VISHAY INTERTECHNOLOGY; MFG_PN01: CRCW0603100KFKEAHP; ROHS: Yes; Tolerance: 1%
TP3 = T_POINT_R: TEST POINT PAD .035 SMT, no part to order; AGILE_PN: 510-75618; CAD_APPROVED: Yes; HEIGHT: 0.1; ROHS: Yes; SILK: 12V0_DESCONN
TP4 TP6-TP10 = T_POINT_R: TEST POINT PAD .035 SMT, no part to order; AGILE_PN: 510-75618; CAD_APPROVED: Yes; HEIGHT: 0.1; ROHS: Yes; SILK: GND
TP5 = T_POINT_R: TEST POINT PAD .035 SMT, no part to order; AGILE_PN: 510-75618; CAD_APPROVED: Yes; HEIGHT: 0.1; ROHS: Yes; SILK: 12V0
TP11 = T_POINT_R: TEST POINT PAD .035 SMT, no part to order; AGILE_PN: 510-75618; CAD_APPROVED: Yes; HEIGHT: 0.1; ROHS: Yes; SILK: 5V0
TP13 = T_POINT_R: TEST POINT PAD .035 SMT, no part to order; AGILE_PN: 510-75618; CAD_APPROVED: Yes; HEIGHT: 0.1; ROHS: Yes; SILK: 3V3
TP14 = T_POINT_R: TEST POINT PAD .035 SMT, no part to order; AGILE_PN: 510-75618; CAD_APPROVED: Yes; HEIGHT: 0.1; ROHS: Yes; SILK: 1V8
TP15 = T_POINT_R: TEST POINT PAD .035 SMT, no part to order; AGILE_PN: 510-75618; CAD_APPROVED: Yes; HEIGHT: 0.1; ROHS: Yes; SILK: SCL
TP17 = T_POINT_R: TEST POINT PAD .035 SMT, no part to order; AGILE_PN: 510-75618; CAD_APPROVED: Yes; HEIGHT: 0.1; ROHS: Yes; SILK: SDA
U6 = VR5500_56P_EP_A: IC PMIC SMPS AND LDO 10A 60V AEC-Q100 QFN56; 3D_Mechanical_Footprint_File: http://fcl.am.freescale.net/ALLEGRO/step/qfn56_0p5_8x8_ep4p39.STEP; AGILE_PN: 312-83637; CAD_APPROVED: Yes; HEIGHT: 1; MFG_NAME01: NXP SEMICONDUCTOR; MFG_PN01: MC33VR5500W5KS; ROHS: NULL; Temp Range: -40°C ~ 125°C; VOLTAGE: 60V

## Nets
GND: C56.1 C57.1 C58.1 C59.1 C60.1 C61.1 C62.1 C63.1 C64.2 C65.2 C66.2 C67.2 C68.2 C69.2 C70.2 C71.2 C72.2 C73.2 C74.2 C75.2 C76.2 C77.2 C78.1 C82.2 C85.2 C87.2 C90.1 C91.2 C92.2 C93.2 C94.2 C95.2 C96.2 C97.2 C98.2 C99.2 C100.2 C105.2 C106.1 D6.A J7.1(SH1) J7.2(SH2) J7.3(SH3) J7.4(SH4) J7.5(SH5) J7.6(SH6) J7.A1 J7.A4 J7.A7 J7.A12 J7.A15 J7.A18 J7.B1 J7.B4 J7.B7 J7.B12 J7.B15 J7.B18 J8.1(SH1) J8.2(SH2) J8.3(SH3) J8.4(SH4) J8.5(SH5) J8.6(SH6) J8.A1 J8.A4 J8.A7 J8.A12 J8.A15 J8.A18 J8.B1 J8.B4 J8.B7 J8.B12 J8.B15 J8.B18 J10.2(B1) Q7.3(SOURCE2) Q9.2(SOURCE) R30.2 R61.2 R64.2 R79.1 R91.1 R93.1 R95.1 R97.2 TP4.1(TP) TP6.1(TP) TP7.1(TP) TP8.1(TP) TP9.1(TP) TP10.1(TP) U6.1(WAKE2) U6.2(NC) U6.20(FIN) U6.21(GND_1) U6.22(GND_2) U6.57(GND_EP) U7.2(A) U7.3(GND) ; also on sheet 1 5 6 7
VCC_1V8_LVDS: C56.2 C60.2 C96.1 C97.1 J7.A5 J7.A6 J8.A5 J8.A6 L5.2 R73.2 R76.2 R77.2 R92.2 R112.2 R116.2 R117.2 TP14.1(TP) U6.17(VCOREMON) U6.39(BUCK1_FB) ; also on sheet 1 7
VCC_3V3_LVDS: C57.2 C61.2 C90.2 C91.1 C92.1 C105.1 D9.A(ANODE) D13.A(ANODE) J7.A13 J7.A14 J8.A13 J8.A14 L4.1 R67.1 R68.1 R74.1 R75.1 TP13.1(TP) U6.4(VDDI2C) U6.9(BUCK3_FB) U6.23(VDDIO) U7.5(VCC) ; also on sheet 1 7
VCC_5V0_LVDS: C58.2 C62.2 C75.1 C76.1 C77.1 C93.1 C95.1 C99.1 C100.1 D11.A(ANODE) J7.A16 J7.A17 J8.A16 J8.A17 R59.2 TP11.1(TP) U6.3(BUCK3_INQ) U6.6(BUCK3_IN) U6.36(BUCK1_IN) U6.48(PRE_FB) U6.53(VBOOST)
VCC_12V0: C64.1 C65.1 D5.A J9.2
VCC_12V0_DESCONN: J9.3 TP3.1(TP) ; also on sheet 7
VCC_12V0_EXT: C66.1 C67.1 J9.1 J10.1(A1)
VCC_12V0_LVDS: C59.2 C63.2 C68.1 C69.1 C70.1 C82.1 D5.C D10.A(ANODE) J7.A8 J7.A9 J8.A8 J8.A9 L1.1 R57.1 TP5.1(TP) U6.50(VSUP1) U6.51(VSUP2)
FS84_BUCK1_SW: L5.1 U6.37(BUCK1_SW)
FS84_BUCK3_SW: L4.2 U6.7(BUCK3_SW)
FS84_DBG: R79.2 U6.8(DBG)
FS84_ERRMON: R64.1 U6.40(NC)
FS84_INTB: C98.1 U6.33(INTB)
FS84_PRE_BOOT: C79.2 U6.46(PRE_BOOT)
FS84_PRE_COMP: C85.1 R63.1 U6.41(PRE_COMP)
FS84_PRE_CSP: L2.2 R59.1 U6.42(PRE_CSP)
FS84_PRE_GHS: Q7.2(GATE1) R60.2 U6.45(PRE_GHS)
FS84_PRE_GLS: Q7.4(GATE2) R61.1 U6.43(PRE_GLS)
FS84_PRE_SW: C79.1 D6.C L2.1 Q7.1(SOURCE1) Q7.5(DRAIN2) R60.1 U6.44(PRE_SW)
FS84_PSYNC: C94.1 R62.2 U6.38(PSYNC)
FS84_SCL: R65.2 U6.10(SCL)
FS84_SDA: R66.2 U6.11(SDA)
FS84_VBOS: C78.2 R62.1 U6.47(VBOS)
FS84_WAKE1: C74.1 R58.2 U6.49(WAKE1)
LVDS0_BL_PWM: J7.B8 R52.2 ; also on sheet 7
LVDS0_CH0_CLK_N: J7.A2 ; also on sheet 7
LVDS0_CH0_CLK_P: J7.A3 ; also on sheet 7
LVDS0_CH0_TS_SCL: J7.B11 J16.3(A2)
LVDS0_CH0_TS_SDA: J7.B10 J16.4(B2)
LVDS0_CH0_TX0_N: J7.B2 ; also on sheet 7
LVDS0_CH0_TX0_P: J7.B3 ; also on sheet 7
LVDS0_CH0_TX1_N: J7.B5 ; also on sheet 7
LVDS0_CH0_TX1_P: J7.B6 ; also on sheet 7
LVDS0_CH0_TX2_N: J7.B13 ; also on sheet 7
LVDS0_CH0_TX2_P: J7.B14 ; also on sheet 7
LVDS0_CH0_TX3_N: J7.B16 ; also on sheet 7
LVDS0_CH0_TX3_P: J7.B17 ; also on sheet 7
LVDS0_CH1_CLK_N: J8.A2 ; also on sheet 7
LVDS0_CH1_CLK_P: J8.A3 ; also on sheet 7
LVDS0_CH1_TS_SCL: J8.B11 J15.3(A2)
LVDS0_CH1_TS_SDA: J8.B10 J15.4(B2)
LVDS0_CH1_TX0_N: J8.B2 ; also on sheet 7
LVDS0_CH1_TX0_P: J8.B3 ; also on sheet 7
LVDS0_CH1_TX1_N: J8.B5 ; also on sheet 7
LVDS0_CH1_TX1_P: J8.B6 ; also on sheet 7
LVDS0_CH1_TX2_N: J8.B13 ; also on sheet 7
LVDS0_CH1_TX2_P: J8.B14 ; also on sheet 7
LVDS0_CH1_TX3_N: J8.B16 ; also on sheet 7
LVDS0_CH1_TX3_P: J8.B17 ; also on sheet 7
LVDS0_TS_INT: J7.B9 R53.2 R73.1 ; also on sheet 7
LVDS_EN_1: J7.A11 R30.1 R110.1 ; also on sheet 7
LVDS_EN_2: R54.1 R97.1 R111.1 ; also on sheet 7
MAX96752_SCL: J15.1(A1) J16.1(A1) R77.1 ; also on sheet 7
MAX96752_SCL1: J15.5(A3) J16.5(A3) R117.1 ; also on sheet 7
MAX96752_SDA: J15.2(B1) J16.2(B1) R76.1 ; also on sheet 7
MAX96752_SDA1: J15.6(B3) J16.6(B3) R116.1 ; also on sheet 7
PMIC_PG: C106.2 R74.2 U6.18(PGOOD) U7.1(~{OE}) ; also on sheet 7
PRE_COMP_RC: C87.1 R63.2
VPI: C71.1 C72.1 L1.2 Q7.6(DRAIN1)
N20069061: J8.B8 R52.1
N20069073: J8.B9 R53.1
N20114256: C73.1 R57.2 R58.1
N20115373: R65.1 R67.2 TP15.1(TP)
N20115434: R66.1 R68.2 TP17.1(TP)
N20116336: R75.2 U6.19(RSTB)
N20169094: J8.A11 R54.2
N20266627: J7.A10 TP26.1(TP)
N20266649: J8.A10 TP28.1(TP)
N20266684: TP29.1(TP) U6.52(NC)
N20266708: TP30.1(TP) U6.54(LDO2)
N20266714: TP31.1(TP) U6.55(LDO1)
N20267097: TP32.1(TP) U6.56(LDO1_IN)
N20273623: D9.C(CATHODE) R90.2
N20273625: D10.C(CATHODE) R91.2
N20273637: Q9.3(DRAIN) R90.1
N20273680: Q9.1(GATE) R92.1
N20273951: D11.C(CATHODE) R93.2
N20274920: D13.C(CATHODE) R95.2
N20331689: R110.2 R111.2 R112.1 U7.4(Y)
N20558280: TP45.1(TP) U6.31(NC)
N20558281: TP43.1(TP) U6.29(AMUX)
N20558282: TP36.1(TP) U6.15(NC)
N20558283: TP44.1(TP) U6.30(NC)
N20558284: TP47.1(TP) U6.34(BUCK2_SW)
N20558285: TP42.1(TP) U6.28(NC)
N20558286: TP33.1(TP) U6.12(NC)
N20558287: TP41.1(TP) U6.27(NC)
N20558288: TP38.1(TP) U6.24(FOUT)
N20558289: TP39.1(TP) U6.25(NC)
N20558290: TP48.1(TP) U6.35(BUCK2_IN)
N20558291: TP37.1(TP) U6.16(VMON1)
N20558292: TP40.1(TP) U6.26(NC)
N20558293: TP34.1(TP) U6.13(NC)
N20558294: TP35.1(TP) U6.14(NC)
N20558295: TP46.1(TP) U6.32(BUCK2_FB)

Not connected (* = marked no-connect by the designer): U6 5(BOOST_LS)*

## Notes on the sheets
sheet 8
- LVDS CONNECTIONS
  (MINI-SAS CONNECTORS)
- Mini-SAS cables cross connect the  Ax pins to Bx (x=1 to 18)
- LED for POWER
- Resistors chosen for 2mA If current
sheet 9
- 12V SELECTION
  EXT OR SRDS CABLE
- EXT 12V CONNECTOR
- PMIC: VR5500
- Q1 Drain and source pins are high current paths.
  Multiple vias and thick traces should be used
- VPRE= 5V
- BUCK1= 1.8V
- BUCK3= 3.3V
- 450KHz Compensation Network
- Place near to PMIC
- VDDI2C
- VDDI2C
- VDDIO
- VDDIO
- VDDI2C
- VDDIO
- 7 Bit Address (Main Logic)= 0x20
